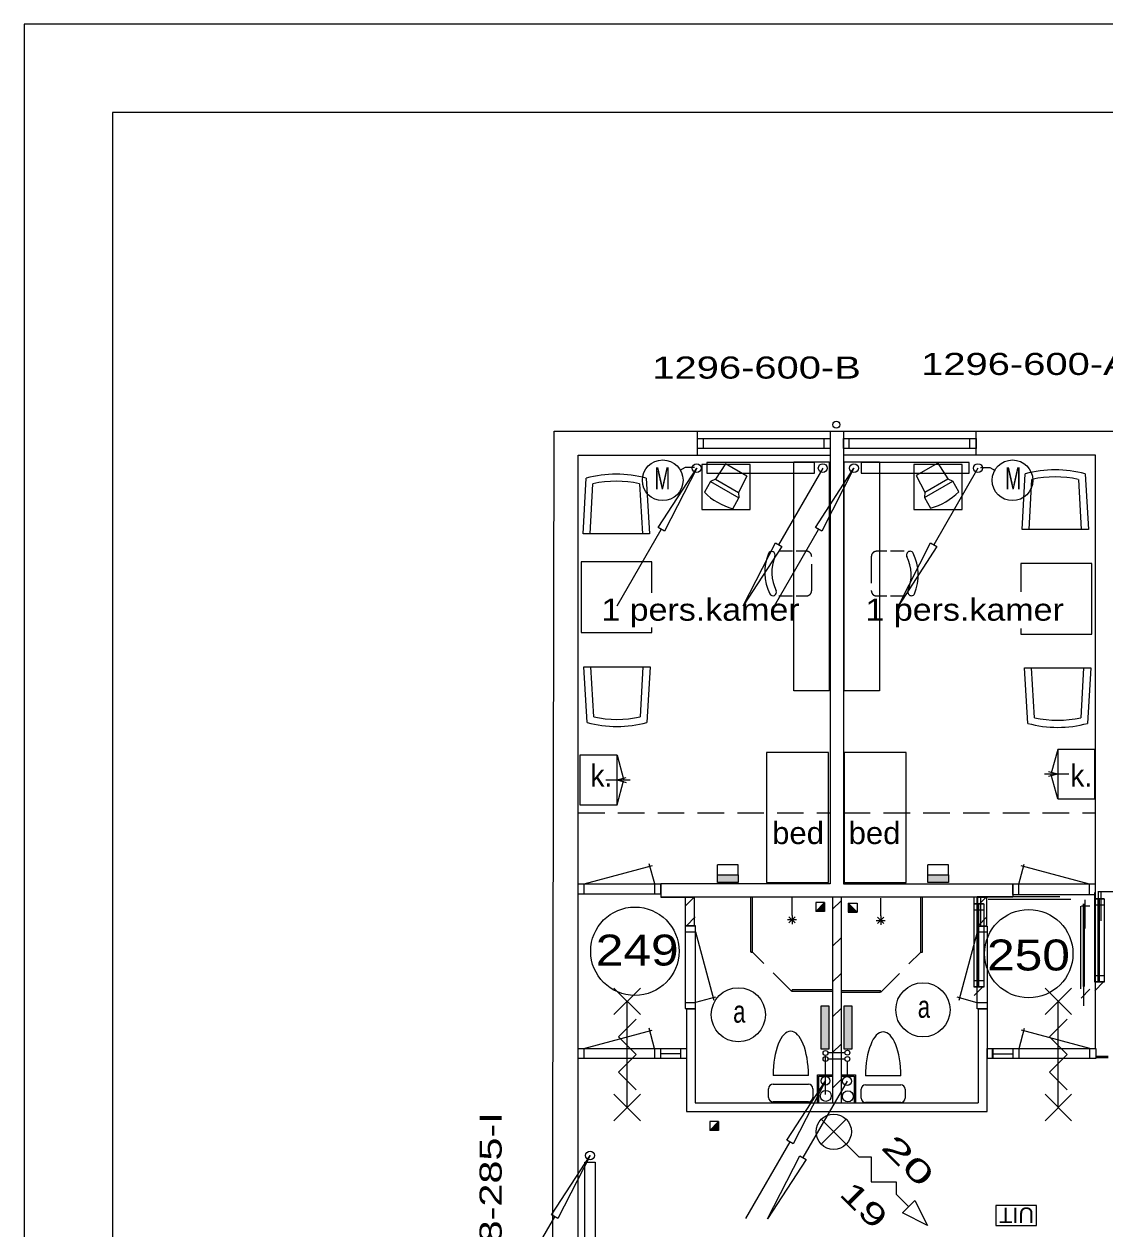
# Model space of a CAD drawing. Extents: x 295824 to 414724, y 24924 to 109024.
# Drawn here: x 295824 to 308047, y 95396 to 109024 of the extents above; entities that cross this region are included whole.
import ezdxf
from ezdxf.enums import TextEntityAlignment as Align

# ---------------------------------------------------------------- set-up
doc = ezdxf.new("R2010")
doc.units = 0
doc.header["$LTSCALE"] = 100
doc.linetypes.add('LONG_DASHED', pattern=[7.5, 6, -1.5])
doc.linetypes.add('MEDIUM_DASHED', pattern=[4.5, 3, -1.5])
for name, color, linetype, lineweight in [('1', 7, 'Continuous', 13), ('16', 7, 'Continuous', 13), ('61', 7, 'Continuous', 13)]:
    doc.layers.add(name, color=color, linetype=linetype, lineweight=lineweight)

msp = doc.modelspace()

# ---------------------------------------------------------------- hatches: boundary and pattern name
at = {"layer": '16'}
for points in [[(303898.7, 99315.2), (303667.2, 99315.2), (303667.2, 99401.7), (303898.7, 99401.7)], [(306277.8, 99315.2), (306046.2, 99315.2), (306046.2, 99401.7), (306277.8, 99401.7)], [(304839.3, 97919.8), (304924.7, 97919.8), (304924.7, 97427.7), (304839.3, 97427.7)], [(305098.5, 97919.8), (305183.9, 97919.8), (305183.9, 97427.7), (305098.5, 97427.7)]]:
    msp.add_hatch(color=256, dxfattribs=at).paths.add_polyline_path(points)
at = {"layer": '61'}
for points in [[(304776.2, 98986.3), (304876.2, 99086.3), (304876.2, 98986.3)], [(305244.4, 98979.7), (305144.4, 99079.7), (305144.4, 98979.7)], [(303578.3, 96509.7), (303678.3, 96609.7), (303678.3, 96509.7)]]:
    msp.add_hatch(color=256, dxfattribs=at).paths.add_polyline_path(points)

# ---------------------------------------------------------------- linework, layer by layer
at = {"layer": '1'}
msp.add_line((295823.6, 109023.8), (295823.6, 24923.8), dxfattribs=at)
for points in [[(414723.6, 109023.8), (304995.6, 109023.8), (295823.6, 109023.8)], [(304995.6, 108023.8), (296823.6, 108023.8), (296823.6, 25923.8), (304995.6, 25923.8)], [(304995.6, 25923.8), (413723.6, 25923.8), (413723.6, 108023.8), (304995.6, 108023.8)]]:
    msp.add_lwpolyline(points, dxfattribs=at)
at = {"layer": '16'}
for p, q in [((304856, 104000.9), (304356, 103134.9)), ((306611.4, 104000.9), (306111.4, 103134.9)), ((302530.5, 102441.9), (303030.5, 103307.9)), ((304309.5, 102441.9), (304809.5, 103307.9)), ((303667.2, 99401.7), (303667.2, 99515.6)), ((306046.2, 99401.7), (306046.2, 99515.6)), ((304886.5, 96917), (304886.5, 97353.4)), ((305106.8, 97388.8), (304915.1, 97388.8)), ((305131.1, 97067.7), (304631.1, 96201.7)), ((303987.2, 95512.9), (304487.2, 96378.9)), ((301324.6, 94667.1), (301824.6, 95533.1))]:
    msp.add_line(p, q, dxfattribs=at)
at = {"layer": '16', "linetype": 'LONG_DASHED'}
for p, q in [((304915.2, 97318.1), (305106.8, 97318.1)), ((305137.7, 97128.8), (305137.7, 97292.3))]:
    msp.add_line(p, q, dxfattribs=at)
at = {"layer": '16'}
for points in [[(303430.5, 104000.9), (303066.5, 103286.9), (302994.5, 103328.9)], [(303543.4, 103945.4), (304762.8, 103945.4), (304762.8, 104063.3), (303543.4, 104063.3)], [(305209.5, 104000.9), (304845.5, 103286.9), (304773.5, 103328.9)], [(305292.4, 103945.4), (306511.7, 103945.4), (306511.7, 104063.3), (305292.4, 104063.3)], [(303956, 102441.9), (304320, 103155.9), (304392, 103113.9)], [(305711.4, 102441.9), (306075.4, 103155.9), (306147.4, 103113.9)], [(303898.7, 99315.2), (303667.2, 99315.2), (303667.2, 99401.7), (303898.7, 99401.7)], [(306277.8, 99315.2), (306046.2, 99315.2), (306046.2, 99401.7), (306277.8, 99401.7)], [(304839.3, 97919.8), (304924.7, 97919.8), (304924.7, 97427.7), (304839.3, 97427.7)], [(305098.5, 97919.8), (305183.9, 97919.8), (305183.9, 97427.7), (305098.5, 97427.7)], [(304887.2, 97071.9), (304523.2, 96357.9), (304451.2, 96399.9)], [(302224.6, 96226.1), (301860.6, 95512.1), (301788.6, 95554.1)], [(304231.1, 95508.7), (304595.1, 96222.7), (304667.1, 96180.7)], [(302281.5, 96151.6), (302281.5, 94932.2), (302163.6, 94932.2), (302163.6, 96151.6)]]:
    msp.add_lwpolyline(points, close=True, dxfattribs=at)
for points in [[(303406.9, 104008.7), (303300.9, 104008.7), (303241.4, 103974.4)], [(306640.4, 104008.7), (306746.4, 104008.7), (306805.9, 103974.4)], [(303898.7, 99401.7), (303898.7, 99515.6), (303667.2, 99515.6)], [(306277.8, 99401.7), (306277.8, 99515.6), (306046.2, 99515.6)]]:
    msp.add_lwpolyline(points, dxfattribs=at)
for centre, radius in [((303045.8, 103863.4), 229.9), ((303430.5, 104000.6), 50), ((304856, 104001.3), 50), ((305209.4, 104000.6), 50), ((306611.4, 104001.3), 50), ((307001.5, 103863.4), 229.9), ((304887.3, 97385.9), 27.9), ((304887.3, 97318.1), 27.9), ((305134.7, 97388.8), 27.9), ((305134.7, 97318.1), 27.9), ((304887.2, 97071.6), 50), ((305131.1, 97068), 50), ((302224.6, 96225.8), 50)]:
    msp.add_circle(centre, radius, dxfattribs=at)
at = {"layer": '61'}
for p, q in [((303441.2, 104147.5), (303441.2, 104417.5)), ((304940.1, 104416.2), (304940.1, 99297.6)), ((305090.1, 104416.2), (305090.1, 99297.6)), ((306589.5, 104147.6), (306589.5, 104417.6)), ((303508, 104223.4), (303508, 104337.2)), ((304873, 104222.8), (304873, 104336.8)), ((305156.5, 104223.7), (305156.5, 104337.7)), ((306520.9, 104223.4), (306520.9, 104337.1)), ((302090.1, 104147.6), (304940.1, 104147.6)), ((302090.1, 97436.8), (302090.1, 104147.6)), ((307940.1, 104147.6), (305090.1, 104147.6)), ((307940.1, 97436.4), (307940.1, 104147.6)), ((303756.2, 104051.5), (303642.5, 103874.6)), ((303998.7, 103911.5), (303756.2, 104051.5)), ((306156.6, 104057.7), (305914.1, 103917.7)), ((306156.6, 104057.7), (306270.2, 103880.8)), ((302145.9, 103258.4), (302180.9, 103887.7)), ((303587.2, 103848.8), (303517.3, 103727.8)), ((303642.5, 103874.6), (303587.2, 103848.8)), ((303587.2, 103848.8), (303907.6, 103663.8)), ((303998.7, 103911.5), (303902.3, 103724.6)), ((305914.1, 103917.7), (306010.4, 103730.8)), ((306005.1, 103670), (306325.5, 103855)), ((306395.5, 103733.7), (306325.5, 103855)), ((307110.4, 103307.6), (307145.3, 103936.9)), ((307190.5, 103307.6), (307221.9, 103873.5)), ((307746.7, 103873.4), (307780.2, 103307.6)), ((302226, 103258.4), (302257.4, 103824.3)), ((302782.2, 103824.2), (302815.7, 103258.4)), ((306010.4, 103730.8), (306005.1, 103670)), ((303837.6, 103542.5), (303907.6, 103663.8)), ((306005.1, 103670), (306075, 103549)), ((304512.2, 103061.4), (304366.1, 103061.4)), ((305776.3, 103060.5), (305623.9, 103060.5)), ((302923.2, 102592.3), (302923.2, 102941.9)), ((304359.7, 102556.4), (304512.2, 102556.4)), ((305623.9, 102555.5), (305770, 102555.5)), ((302123.2, 102141.9), (302923.2, 102141.9)), ((302923.2, 102141.9), (302923.2, 102198.9)), ((307097.5, 102189), (307097.5, 102122.2)), ((302266.4, 101187.6), (302232.9, 101753.4)), ((302822.6, 101753.4), (302791.2, 101187.5)), ((302902.7, 101753.4), (302867.8, 101124.1)), ((307250.5, 101177.8), (307217, 101743.6)), ((307806.7, 101743.6), (307775.3, 101177.7)), ((307886.9, 101743.6), (307851.9, 101114.3)), ((302529.4, 100753.9), (302602.4, 100481.2)), ((307513.3, 100819), (307441, 100549.1)), ((302403.5, 100473.9), (302679.5, 100473.9)), ((302529.4, 100473.9), (302632.8, 100501.6)), ((302529.4, 100473.9), (302633.2, 100446.1)), ((302529.4, 100193.9), (302601.7, 100463.8)), ((307639.2, 100539), (307363.2, 100539)), ((307513.3, 100539), (307409.5, 100566.8)), ((307513.3, 100539), (307409.9, 100511.3)), ((307513.3, 100259), (307440.2, 100531.7)), ((302156.8, 99298.4), (302929.6, 99505.5)), ((302955.3, 99299.1), (302894.5, 99525.9)), ((307075, 99295.4), (307135.8, 99522.2)), ((307873.5, 99294.8), (307100.7, 99501.8)), ((302157.6, 99183.8), (302157.6, 99297.8)), ((302957.6, 99183.8), (302957.6, 99297.8)), ((303024.6, 99183.8), (303024.6, 99297.8)), ((304940.1, 99297.6), (303025.4, 99297.6)), ((303025.4, 99297.6), (303025.4, 99147.6)), ((305090.1, 99297.6), (307004.9, 99297.6)), ((307004.9, 99297.6), (307004.9, 99147.6)), ((307005.7, 99180.1), (307005.7, 99294.1)), ((307072.7, 99180.1), (307072.7, 99294.1)), ((307872.7, 99180.1), (307872.7, 99294.1)), ((303025.4, 99147.6), (303315.1, 99147.6)), ((307004.9, 99147.6), (303025.4, 99147.6)), ((303301.8, 99046.8), (303401.5, 99146.5)), ((303407.4, 98824.2), (303407.4, 99147)), ((304058.7, 99148.6), (304058.7, 98528.1)), ((304508.5, 98942.1), (304508.5, 99142.1)), ((304966.4, 99147.6), (304966.4, 96822.6)), ((304966.9, 99011.5), (305062.7, 99107.3)), ((305062.7, 99147.6), (305062.7, 96822.6)), ((305512.1, 98935.5), (305512.1, 99135.5)), ((305961.9, 99142), (305961.9, 98521.5)), ((306567.3, 98823), (306567.3, 99147)), ((307536, 99151.2), (306602, 99151.2)), ((306602.2, 98823), (306602.2, 99147)), ((306602.2, 99147), (306712.2, 99147)), ((306603.9, 99046.8), (306703.6, 99146.5)), ((306606, 99149), (306720, 99149)), ((306610, 98823), (306610, 99147)), ((306642.2, 98824.2), (306642.2, 99148.3)), ((306712.2, 98823), (306712.2, 99147)), ((307660.1, 99123.3), (306726.1, 99123.3)), ((307822.7, 98795.1), (307822.7, 99119.2)), ((307931.5, 98878.7), (307931.5, 99202.8)), ((308038.1, 99127.8), (307932.9, 99127.8)), ((308900.2, 99206.9), (307966.2, 99206.9)), ((307971.6, 98191.8), (307971.6, 99124.2)), ((307974.2, 98878.7), (307974.2, 99202.8)), ((307987.4, 98191.8), (307987.4, 99124.2)), ((308006.5, 98879.9), (308006.5, 99204)), ((308044.1, 98191.8), (308044.1, 99124.2)), ((304508.5, 98942.1), (304508.5, 98842.1)), ((306679.9, 99001.5), (306565.9, 99001.5)), ((306673.9, 99072.1), (306568.6, 99072.1)), ((306607.4, 98136.1), (306607.4, 99068.5)), ((306623.2, 98136.1), (306623.2, 99068.5)), ((306679.9, 98136.1), (306679.9, 99068.5)), ((307775.7, 98110.9), (307775.7, 99044.9)), ((307877.9, 99045.7), (307783.2, 99045.7)), ((307804.5, 98138.8), (307804.5, 99072.8)), ((307815.5, 98138.8), (307815.5, 99072.8)), ((308044.1, 99057.2), (307930.1, 99057.2)), ((303303.3, 98823), (303413.2, 98823)), ((303314.1, 98824.2), (303413.8, 98923.9)), ((304558.5, 98892.1), (304458.5, 98892.1)), ((304543.9, 98927.4), (304473.1, 98856.7)), ((304543.9, 98856.7), (304473.1, 98927.4)), ((305462.1, 98885.5), (305562.1, 98885.5)), ((305476.7, 98920.9), (305547.4, 98850.2)), ((305476.7, 98850.2), (305547.4, 98920.9)), ((305512.1, 98935.5), (305512.1, 98835.5)), ((306601.5, 98819.4), (306715.5, 98819.4)), ((306602.2, 98823), (306712.2, 98823)), ((306612.5, 98824.2), (306712.2, 98923.9)), ((306714.9, 98819.4), (306714.9, 97885.4)), ((307806, 98850), (307806, 97917.6)), ((303301.5, 98756.7), (303415.5, 98756.7)), ((303418.6, 98757.4), (303625.7, 97984.7)), ((304966.9, 98593.4), (305062.7, 98689.2)), ((306602.9, 98753.2), (306395.8, 97980.5)), ((306714.9, 98752.4), (306600.9, 98752.4)), ((304046.5, 98526.9), (304064.5, 98526.9)), ((304966.9, 98188.8), (305062.7, 98284.6)), ((306679.9, 98201.5), (306565.9, 98201.5)), ((306667.2, 98134), (306567.5, 98034.3)), ((306678, 98135.2), (306568.1, 98135.2)), ((306715.1, 98215), (306715.1, 97322.7)), ((308044.1, 98257.2), (307930.1, 98257.2)), ((308031.5, 98189.7), (307931.8, 98090)), ((308042.3, 98190.9), (307932.3, 98190.9)), ((302794.8, 98119.9), (302494.8, 97819.9)), ((302494.8, 98119.9), (302794.8, 97819.9)), ((303419.3, 97959), (303646.1, 98019.8)), ((304966.4, 98098.6), (304509.5, 98098.6)), ((304509.5, 98080.6), (304509.5, 98098.6)), ((304966.4, 98080.6), (304509.5, 98080.6)), ((305061.5, 98074), (305511, 98074)), ((305061.9, 98092), (305511, 98092)), ((305511, 98074), (305511, 98092)), ((306602.2, 97954.8), (306375.4, 98015.6)), ((307670.3, 98119.9), (307370.3, 97819.9)), ((307370.3, 98119.9), (307670.3, 97819.9)), ((307878.1, 98106.1), (307778.4, 98006.4)), ((302644.8, 96769.9), (302644.8, 97969.9)), ((303301.5, 97956.7), (303415.5, 97956.7)), ((303315.1, 97886.1), (303315.1, 97437.5)), ((303315.1, 97886.1), (303412.7, 97886.1)), ((304966.9, 97792.8), (305062.7, 97888.6)), ((306714.9, 97952.4), (306600.9, 97952.4)), ((306612.7, 97884.6), (306612.7, 96822.6)), ((306612.7, 97884.6), (306707.4, 97884.6)), ((307520.3, 96769.9), (307520.3, 97969.9)), ((302155.5, 97437.3), (302928.3, 97644.4)), ((302953.9, 97437.9), (302893.2, 97664.8)), ((307078.8, 97437.9), (307139.5, 97664.8)), ((307877.2, 97437.3), (307104.4, 97644.4)), ((304966.9, 97389.4), (305062.7, 97485.2)), ((302090.1, 94558.1), (302090.1, 97322)), ((302156.3, 97322.7), (302156.3, 97436.7)), ((302956.3, 97322.7), (302956.3, 97436.7)), ((303023.3, 97322.7), (303023.3, 97436.7)), ((303249.3, 97376.8), (303023.3, 97376.8)), ((303249.3, 97322.7), (303249.3, 97436.7)), ((306775.9, 97322.7), (306775.9, 97436.7)), ((306783.4, 97322.7), (306783.4, 97436.7)), ((306783.4, 97376.8), (307009.4, 97376.8)), ((307009.4, 97322.7), (307009.4, 97436.7)), ((307076.4, 97322.7), (307076.4, 97436.7)), ((307876.4, 97322.7), (307876.4, 97436.7)), ((307944.7, 97348.9), (308085.9, 97348.9)), ((307944.7, 97333.9), (308085.9, 97333.9)), ((304694.2, 97131.8), (304294.2, 97131.8)), ((304294.2, 97031.8), (304694.2, 97031.8)), ((304797.6, 96823.1), (304797.6, 97139.3)), ((304797.6, 97139.3), (304965.6, 97139.3)), ((304812.6, 97123.1), (304965, 97123.1)), ((304812.6, 96823.1), (304812.6, 97123.1)), ((304966.9, 96988.5), (305062.7, 97084.3)), ((305062.7, 97122.6), (305212.7, 97122.6)), ((305212.7, 97122.6), (305212.7, 96822.6)), ((305739.5, 97125.6), (305339.5, 97125.6)), ((302794.8, 96919.9), (302494.8, 96619.9)), ((302494.8, 96919.9), (302794.8, 96619.9)), ((304244.2, 96881.8), (304244.2, 96981.8)), ((304744.2, 96981.8), (304744.2, 96881.8)), ((305289.5, 96875.6), (305289.5, 96975.6)), ((305339.5, 97025.6), (305739.5, 97025.6)), ((305789.5, 96975.6), (305789.5, 96875.6)), ((307670.3, 96919.9), (307370.3, 96619.9)), ((307370.3, 96919.9), (307670.3, 96619.9)), ((304694.2, 96831.8), (304294.2, 96831.8)), ((305739.5, 96825.6), (305339.5, 96825.6)), ((305121.5, 96636.6), (304838.6, 96353.8))]:
    msp.add_line(p, q, dxfattribs=at)
at = {"layer": '61', "linetype": 'MEDIUM_DASHED'}
for p, q in [((304670.8, 103061.4), (304554.5, 103061.4)), ((305581.5, 103060.5), (305465.3, 103060.5)), ((304730.8, 102616.4), (304730.8, 103001.4)), ((305405.3, 103000.5), (305405.3, 102615.5)), ((304554.5, 102556.4), (304670.8, 102556.4)), ((305465.3, 102555.5), (305581.5, 102555.5)), ((302090.1, 100101), (304939.8, 100101)), ((305093, 100101), (307940.7, 100101)), ((304507.5, 98081), (304060.6, 98527.9)), ((305513.1, 98074.4), (305960, 98521.3))]:
    msp.add_line(p, q, dxfattribs=at)
at = {"layer": '61'}
for points in [[(301796.6, 92184.5), (301820.1, 104417.6), (332210.1, 104417.6)], [(302858.6, 103887.7), (302895.9, 103258.4), (302145.9, 103258.4)], [(303642.5, 103874.6), (303902.3, 103724.6), (303907.6, 103663.8)], [(306010.4, 103730.8), (306270.2, 103880.8), (306325.5, 103855)], [(307823.1, 103936.8), (307860.3, 103307.6), (307110.4, 103307.6)], [(302923.2, 102941.9), (302123.2, 102941.9), (302123.2, 102141.9)], [(307097.5, 102122.2), (307897.5, 102122.2), (307897.5, 102922.2), (307097.5, 102922.2), (307097.5, 102602.1)], [(302190, 101124.2), (302152.8, 101753.4), (302902.7, 101753.4)], [(307174.1, 101114.3), (307136.9, 101743.6), (307886.9, 101743.6)], [(302090.6, 99183.8), (302090.6, 99297.8), (303024.6, 99297.8)], [(303024.6, 99183.8), (302090.6, 99183.8), (302090.6, 99297.8)], [(307939.7, 99180.1), (307939.7, 99294.1), (307005.7, 99294.1)], [(307005.7, 99180.1), (307939.7, 99180.1), (307939.7, 99294.1)], [(303303.3, 98823), (303303.3, 99147), (303407.4, 99147)], [(304040.7, 99148.6), (304040.7, 98528.1), (304058.7, 98528.1)], [(304876.2, 99086.3), (304876.2, 98986.3), (304776.2, 98986.3)], [(305144.4, 99079.7), (305144.4, 98979.7), (305244.4, 98979.7)], [(305979.9, 99142), (305979.9, 98521.5), (305961.9, 98521.5)], [(303412.7, 97886.1), (303412.7, 96822.6), (306612.7, 96822.6)], [(302744.8, 96969.9), (302544.8, 97169.9), (302744.8, 97369.9), (302544.8, 97569.9), (302744.8, 97769.9)], [(307620.3, 96969.9), (307420.3, 97169.9), (307620.3, 97369.9), (307420.3, 97569.9), (307620.3, 97769.9)], [(303315.1, 97322), (303315.1, 96722.6), (306715.1, 96722.6), (306715.1, 97322.6)], [(305062.7, 97137.6), (305227.7, 97137.6), (305227.7, 96822.6)], [(304838.6, 96636.6), (305262.9, 96212.3), (305404.3, 96212.3), (305404.3, 95929.5), (305687.1, 95929.5), (305687.1, 95788.1), (305828.6, 95646.7)], [(303678.3, 96609.7), (303678.3, 96509.7), (303578.3, 96509.7)]]:
    msp.add_lwpolyline(points, dxfattribs=at)
for points in [[(303441.2, 104223.2), (303441.2, 104337.2), (304939.9, 104337.2), (304939.9, 104223.2)], [(305090.2, 104223.4), (305090.2, 104337.4), (306589.6, 104337.4), (306589.6, 104223.4)], [(304033.8, 104041.8), (303487.6, 104041.8), (303487.6, 103533.7), (304033.8, 103533.7)], [(304529.6, 101480.4), (304529.6, 104072.3), (304929.6, 104072.3), (304929.6, 101480.4)], [(305099.7, 101480.4), (305099.7, 104072.3), (305499.7, 104072.3), (305499.7, 101480.4)], [(306432.5, 104041.8), (305886.3, 104041.8), (305886.3, 103533.7), (306432.5, 103533.7)], [(302109.4, 100193.9), (302529.4, 100193.9), (302529.4, 100753.9), (302109.4, 100753.9)], [(304220.2, 99313.9), (304920.2, 99313.9), (304920.2, 100783.9), (304220.2, 100783.9)], [(305100.1, 99313.9), (305800.1, 99313.9), (305800.1, 100783.9), (305100.1, 100783.9)], [(307933.3, 100819), (307513.3, 100819), (307513.3, 100259), (307933.3, 100259)], [(304876.2, 99086.3), (304776.2, 99086.3), (304776.2, 98986.3)], [(304776.2, 98986.3), (304876.2, 99086.3), (304876.2, 98986.3)], [(305144.4, 99079.7), (305244.4, 99079.7), (305244.4, 98979.7)], [(305244.4, 98979.7), (305144.4, 99079.7), (305144.4, 98979.7)], [(308044.1, 99125.2), (307930.1, 99125.2), (307930.1, 98191.2), (308044.1, 98191.2)], [(306679.9, 99069.4), (306565.9, 99069.4), (306565.9, 98135.4), (306679.9, 98135.4)], [(303301.5, 97888.7), (303415.5, 97888.7), (303415.5, 98822.7), (303301.5, 98822.7)], [(306714.9, 98819.4), (306714.9, 97885.4), (306600.9, 97885.4), (306600.9, 98819.4)], [(302089.3, 97322.7), (302089.3, 97436.7), (303315.7, 97436.7), (303315.7, 97322.7)], [(302089.3, 97322.7), (302089.3, 97436.7), (303315.7, 97436.7), (303315.7, 97322.7)], [(306716.4, 97322.7), (306716.4, 97436.7), (307943.4, 97436.7), (307943.4, 97322.7)], [(303678.3, 96609.7), (303578.3, 96609.7), (303578.3, 96509.7)], [(303578.3, 96509.7), (303678.3, 96609.7), (303678.3, 96509.7)], [(305757.9, 95575.9), (305899.3, 95717.4), (306040.7, 95434.5)], [(307273.8, 95659.3), (306814.1, 95659.3), (306814.1, 95434.7), (307273.8, 95434.7)]]:
    msp.add_lwpolyline(points, close=True, dxfattribs=at)
for centre, radius in [((305009.5, 104492.8), 40), ((302731.4, 98536.8), 500), ((307186, 98509), 500), ((303900.9, 97817.9), 306.3), ((305989, 97873.7), 306.3), ((304890.2, 96900.6), 62.5), ((305140.2, 96895), 62.5), ((304980, 96495.2), 200)]:
    msp.add_circle(centre, radius, dxfattribs=at)
for centre, radius, start, end in [((307484.1, 102697.1), 1285.2, 74.70731, 105.28507), ((302519.7, 102648), 1285.2, 74.70731, 105.28507), ((302519.7, 102648), 1205.2, 77.41626, 102.56606), ((307484.1, 102697.1), 1205.2, 77.41626, 102.56606), ((304031.6, 104247.1), 730.8, 225.27982, 254.60839), ((305882.4, 104254), 730.8, 285.27982, 314.60839), ((304765.8, 102824.6), 565.2, 157.99711, 205.84523), ((304277.7, 103019), 40, 334.24441, 154.24441), ((305843.4, 103020.5), 40, 25.75559, 205.75559), ((305370.3, 102792.3), 565.2, 337.99711, 25.84523), ((304765.8, 102824.6), 485.2, 158.65343, 205.61348), ((305370.3, 102792.3), 485.2, 338.65343, 25.61348), ((304292.7, 102596.4), 40, 205.75559, 25.75559), ((305858.3, 102597.9), 40, 154.24441, 334.24441), ((302528.9, 102363.9), 1285.2, 254.70731, 285.28507), ((302528.9, 102363.9), 1205.2, 257.41626, 282.56606), ((307513.1, 102354), 1205.2, 257.41626, 282.56606), ((307513.1, 102354), 1285.2, 254.70731, 285.28507), ((304294.2, 96981.8), 50, 90, 180), ((304694.2, 96981.8), 50, 0, 90), ((305339.5, 96975.6), 50, 90, 180), ((305739.5, 96975.6), 50, 0, 90), ((304294.2, 96881.8), 50, 180, 270), ((304694.2, 96881.8), 50, 270, 0), ((305339.5, 96875.6), 50, 180, 270), ((305739.5, 96875.6), 50, 270, 0)]:
    msp.add_arc(centre, radius, start, end, dxfattribs=at)
at = {"layer": '61', "linetype": 'MEDIUM_DASHED'}
for centre, start, end in [((304670.8, 103001.4), 0, 90), ((305465.3, 103000.5), 90, 180), ((304670.8, 102616.4), 270, 0), ((305465.3, 102615.5), 180, 270)]:
    msp.add_arc(centre, 60, start, end, dxfattribs=at)
at = {"layer": '61'}
for centre in [(304494.2, 97131.8), (305539.5, 97125.6)]:
    msp.add_ellipse(centre, major_axis=(0, 500), ratio=0.4, start_param=4.712389, end_param=7.8539816, dxfattribs=at)

# ---------------------------------------------------------------- texts
at = {"layer": '16'}
for s, width, p in [('1296-600-B', 1.35, (302928.5, 105013.7)), ('1296-600-A', 1.35, (305969.1, 105054.9)), ('M', 0.65, (302951.8, 103760.3)), ('M', 0.65, (306918.3, 103760.3))]:
    msp.add_text(s, height=250, dxfattribs=dict(at, width=width)).set_placement(p)
at = {"layer": '16', "width": 1.4}
msp.add_text('2268-285-I', height=250, rotation=90, dxfattribs=at).set_placement((301224.6, 94451))
at = {"layer": '61'}
for s, width, p in [('1 pers.kamer', 1.15, (302351.6, 102275.4)), ('1 pers.kamer', 1.15, (305339.5, 102275.4)), ('k.', 0.95, (302229.1, 100398.6)), ('k.', 0.95, (307655.7, 100398.6)), ('bed', 1.05, (304283.8, 99749.1)), ('bed', 1.05, (305148.9, 99749.1)), ('a', 0.75, (303842.9, 97728.8)), ('a', 0.75, (305931, 97784.5))]:
    msp.add_text(s, height=250, dxfattribs=dict(at, width=width)).set_placement(p)
at = {"layer": '61', "width": 1.2}
for s, p in [('249', (302757.7, 98374.8)), ('250', (307183, 98319.1))]:
    msp.add_text(s, height=350, dxfattribs=at).set_placement(p, align=Align.CENTER)
at = {"layer": '61'}
for s, height, rotation, width, p in [('20', 250, 315, 1.75, (305502.6, 96310)), ('19', 250, 315, 1.55, (305030.3, 95781.5)), ('UIT', 175, 180, 1.05, (307247, 95637.9))]:
    msp.add_text(s, height=height, rotation=rotation, dxfattribs=dict(at, width=width)).set_placement(p)

doc.saveas('drawing.dxf')
